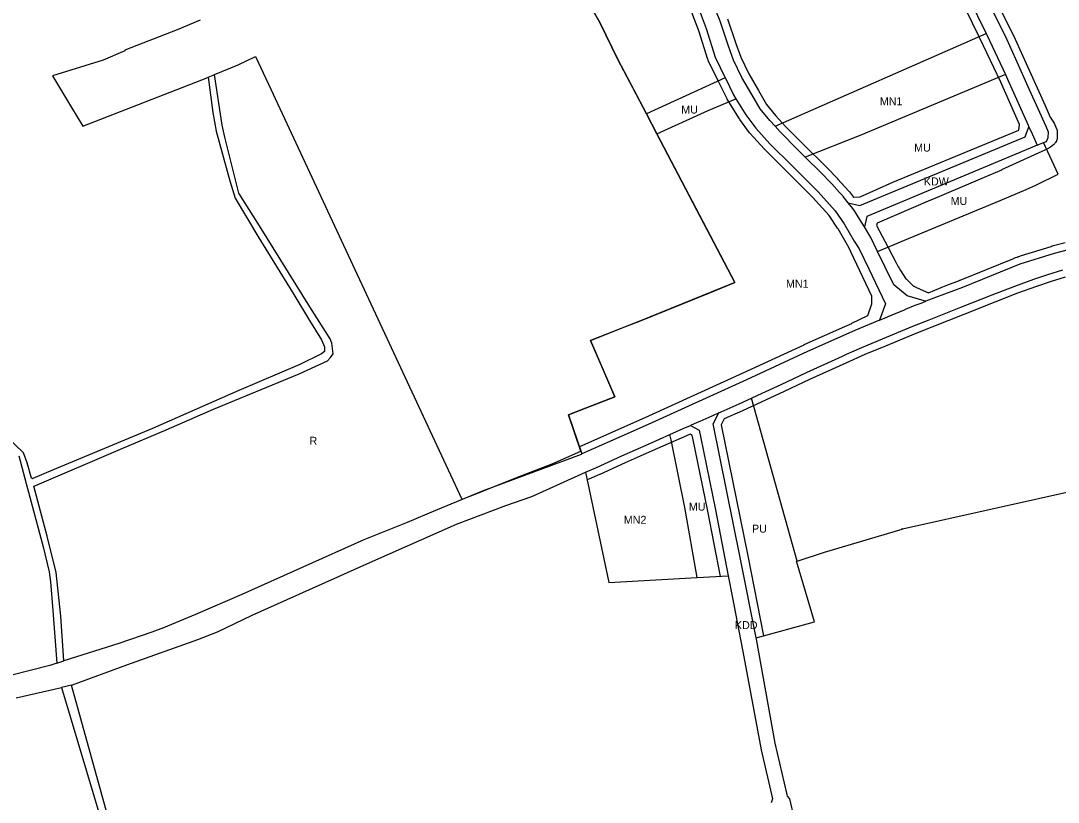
# Model space of a CAD drawing. Extents: x 7435758 to 7439981, y 5550649 to 5554049.
# Drawn here: x 7436433 to 7437107, y 5551221 to 5551729 of the extents above; entities that cross this region are included whole.
import ezdxf

# ---------------------------------------------------------------- set-up
doc = ezdxf.new("R2010")
doc.units = 0
for name, color, linetype in [('info', 7, 'Continuous'), ('linie_rozgraniczające', 7, 'Continuous'), ('linie_zabudowy_nieprzekraczalne', 7, 'Continuous'), ('oznaczenia_przeznaczen', 7, 'Continuous')]:
    doc.layers.add(name, color=color, linetype=linetype)

msp = doc.modelspace()

# ---------------------------------------------------------------- linework, layer by layer
at = {"layer": 'info'}
for p, q in [((7436549.92, 5551729.75), (7436534.97, 5551723.42)), ((7436554.78, 5551692.57), (7436555, 5551692.66)), ((7436594.25, 5551688.18), (7436720, 5551418.39)), ((7436839.8, 5551668.84), (7436830.9, 5551685.83)), ((7436846.57, 5551655.92), (7436839.8, 5551668.84)), ((7436872.6, 5551606.23), (7436846.57, 5551655.92)), ((7436834.79, 5551533.96), (7436880.27, 5551552.36)), ((7436825.84, 5551530.4), (7436834.79, 5551533.96)), ((7436819.25, 5551484.94), (7436811.4, 5551503.25)), ((7436808.77, 5551480.86), (7436819.25, 5551484.94))]:
    msp.add_line(p, q, dxfattribs=at)
for points in [[(7436830.9, 5551685.83), (7436821.23, 5551704.3), (7436809.54, 5551728.26), (7436800.79, 5551743.61)], [(7436534.97, 5551723.42), (7436500.87, 5551710.27), (7436500.89, 5551709.81), (7436486.9, 5551703.76), (7436453.97, 5551693.56), (7436466.32, 5551673), (7436473.75, 5551660.92), (7436554.78, 5551692.57)], [(7436559.23, 5551694.45), (7436574.58, 5551700.76), (7436585.89, 5551706.11), (7436585.89, 5551706.11), (7436594.25, 5551688.18)], [(7436555, 5551692.66), (7436558.29, 5551694.06), (7436559.23, 5551694.45)], [(7436880.27, 5551552.36), (7436897.23, 5551559.22), (7436872.6, 5551606.23)], [(7436811.4, 5551503.25), (7436803.56, 5551521.54), (7436825.84, 5551530.4)], [(7436797.24, 5551449.59), (7436789.24, 5551473.16), (7436800.3, 5551477.56), (7436808.77, 5551480.86)], [(7436733.94, 5551423.92), (7436756.16, 5551432.67), (7436778.56, 5551441.5), (7436797.24, 5551449.59)], [(7436720, 5551418.39), (7436720.74, 5551418.7), (7436733.47, 5551423.74)], [(7436733.47, 5551423.74), (7436733.75, 5551423.85), (7436733.94, 5551423.92)]]:
    msp.add_lwpolyline(points, dxfattribs=at)
at = {"layer": 'linie_rozgraniczające'}
for p, q in [((7436780.9, 5551778.49), (7436809.54, 5551728.26)), ((7437073.91, 5551717.41), (7437057.78, 5551750.11)), ((7436887.83, 5551729.05), (7436879.8, 5551748.53)), ((7437047.32, 5551748.47), (7437060.55, 5551721.15)), ((7436874, 5551736.55), (7436878.59, 5551724.44)), ((7436809.54, 5551728.26), (7436821.23, 5551704.3)), ((7436878.59, 5551724.44), (7436884.53, 5551705.83)), ((7436893.13, 5551712.87), (7436887.83, 5551729.05)), ((7436923.4, 5551660.79), (7437060.54, 5551721.14)), ((7437060.54, 5551721.14), (7437060.55, 5551721.14)), ((7437060.55, 5551721.15), (7437060.55, 5551721.14)), ((7437060.55, 5551721.14), (7437060.96, 5551720.27)), ((7437060.96, 5551720.27), (7437073.16, 5551694.4)), ((7437079.77, 5551704.39), (7437073.91, 5551717.41)), ((7436896.5, 5551703.72), (7436893.13, 5551712.87)), ((7436821.23, 5551704.3), (7436839.8, 5551668.84)), ((7436884.53, 5551705.83), (7436891.02, 5551692.32)), ((7436901.88, 5551692.46), (7436896.5, 5551703.72)), ((7437088.75, 5551684.44), (7437079.77, 5551704.39)), ((7436555, 5551692.66), (7436558.03, 5551669.7)), ((7436564.11, 5551661.5), (7436559.23, 5551694.45)), ((7436891.02, 5551692.32), (7436839.8, 5551668.84)), ((7436891.02, 5551692.32), (7436891.1, 5551692.16)), ((7436891.1, 5551692.16), (7436896.46, 5551681.18)), ((7436908.33, 5551681.52), (7436901.88, 5551692.46)), ((7437073.16, 5551694.4), (7436979.07, 5551654.95)), ((7437073.16, 5551694.4), (7437074.53, 5551691.49)), ((7437074.53, 5551691.49), (7437087.82, 5551661.62)), ((7437094.25, 5551672.21), (7437088.75, 5551684.44)), ((7436879.91, 5551671.09), (7436898.01, 5551678.68)), ((7436896.46, 5551681.18), (7436898.01, 5551678.68)), ((7436898.01, 5551678.68), (7436904.5, 5551668.25)), ((7436913.63, 5551672.17), (7436908.33, 5551681.52)), ((7436558.03, 5551669.7), (7436560.18, 5551657.72)), ((7436846.57, 5551655.92), (7436879.91, 5551671.09)), ((7436919.95, 5551664.5), (7436913.63, 5551672.17)), ((7437099.45, 5551660.63), (7437094.25, 5551672.21)), ((7436839.8, 5551668.84), (7436846.57, 5551655.92)), ((7436904.5, 5551668.25), (7436910.87, 5551659.49)), ((7436923.4, 5551660.79), (7436919.95, 5551664.5)), ((7436560.18, 5551657.72), (7436569.22, 5551625.29)), ((7436565.91, 5551653.74), (7436564.11, 5551661.5)), ((7436846.57, 5551655.92), (7436897.23, 5551559.22)), ((7436910.87, 5551659.49), (7436920.02, 5551649.48)), ((7436926.67, 5551657.26), (7436923.4, 5551660.79)), ((7436938.07, 5551645.7), (7436926.67, 5551657.26)), ((7437085.84, 5551653.87), (7437088.31, 5551660.53)), ((7437087.82, 5551661.62), (7437087.92, 5551661.39)), ((7437087.92, 5551661.39), (7437088.31, 5551660.53)), ((7437088.31, 5551660.53), (7437090.46, 5551655.79)), ((7437090.46, 5551655.79), (7437093.78, 5551648.48)), ((7437101.07, 5551657), (7437099.45, 5551660.63)), ((7437100.85, 5551653.56), (7437101.11, 5551656.93)), ((7437101.11, 5551656.93), (7437101.07, 5551657)), ((7436574.95, 5551617.32), (7436565.91, 5551653.74)), ((7436920.02, 5551649.48), (7436934.54, 5551635.04)), ((7436979.07, 5551654.95), (7436943.06, 5551640.76)), ((7436978.46, 5551609.25), (7437085.84, 5551653.87)), ((7437093.78, 5551648.48), (7437097.85, 5551650.19)), ((7437097.85, 5551650.19), (7437099.72, 5551650.97)), ((7437100.68, 5551644.24), (7437097.85, 5551650.19)), ((7437099.72, 5551650.97), (7437100.85, 5551653.56)), ((7436943.06, 5551640.76), (7436938.07, 5551645.7)), ((7437089.16, 5551646.55), (7436983.06, 5551602.18)), ((7437093.78, 5551648.48), (7437089.16, 5551646.55)), ((7437107.34, 5551629.66), (7437100.68, 5551644.24)), ((7436953.44, 5551630.48), (7436943.06, 5551640.76)), ((7436934.54, 5551635.04), (7436951.34, 5551618.24)), ((7436959.58, 5551624.12), (7436953.44, 5551630.48)), ((7437093.23, 5551622.83), (7437107.34, 5551629.66)), ((7436569.22, 5551625.29), (7436572.53, 5551614.07)), ((7436959.6, 5551624.1), (7436959.58, 5551624.12)), ((7436960.28, 5551623.38), (7436959.6, 5551624.1)), ((7436965.37, 5551617.79), (7436960.28, 5551623.38)), ((7437086.63, 5551619.64), (7437093.23, 5551622.83)), ((7436588.35, 5551596.16), (7436574.95, 5551617.32)), ((7436951.34, 5551618.24), (7436962.5, 5551605.85)), ((7436967.41, 5551615.56), (7436965.37, 5551617.79)), ((7436967.72, 5551615.21), (7436967.41, 5551615.56)), ((7436970.99, 5551611.01), (7436967.72, 5551615.21)), ((7437069.6, 5551612.53), (7437086.63, 5551619.64)), ((7436572.53, 5551614.07), (7436588.07, 5551588.32)), ((7436973.84, 5551607.33), (7436970.99, 5551611.01)), ((7436970.99, 5551611.01), (7436978.46, 5551609.25)), ((7437007.51, 5551586.69), (7437069.6, 5551612.53)), ((7436962.5, 5551605.85), (7436968.31, 5551597.34)), ((7436974.93, 5551605.94), (7436973.84, 5551607.33)), ((7436978.45, 5551600.25), (7436974.93, 5551605.94)), ((7436983.06, 5551602.18), (7436981.47, 5551595.36)), ((7436621.2, 5551543.41), (7436588.35, 5551596.16)), ((7436968.31, 5551597.34), (7436974.77, 5551586.13)), ((7436981.47, 5551595.36), (7436978.45, 5551600.25)), ((7436985.65, 5551588.61), (7436981.47, 5551595.36)), ((7436588.07, 5551588.32), (7436610.73, 5551551.38)), ((7436990.03, 5551579.48), (7436985.65, 5551588.61)), ((7436974.77, 5551586.13), (7436978.12, 5551581.08)), ((7436990.03, 5551579.48), (7437007.51, 5551586.69)), ((7436978.12, 5551581.08), (7436984.26, 5551568.21)), ((7436994.96, 5551569.19), (7436990.03, 5551579.48)), ((7437104.79, 5551578.17), (7437082.49, 5551571.18)), ((7437113.83, 5551580.57), (7437104.79, 5551578.17)), ((7436984.26, 5551568.21), (7436995.06, 5551545.39)), ((7437000.48, 5551557.66), (7436994.96, 5551569.19)), ((7437082.49, 5551571.18), (7437045.16, 5551556.09)), ((7437079.18, 5551556.96), (7437091.55, 5551561.49)), ((7437091.55, 5551561.49), (7437100.72, 5551564.52)), ((7437100.72, 5551564.52), (7437110.46, 5551567.5)), ((7436897.23, 5551559.22), (7436834.79, 5551533.96)), ((7437009.3, 5551550.61), (7437000.48, 5551557.66)), ((7437045.16, 5551556.09), (7437027.68, 5551549.46)), ((7437064.45, 5551551.19), (7437079.18, 5551556.96)), ((7436610.73, 5551551.38), (7436620.92, 5551534.56)), ((7437020.18, 5551547.38), (7437009.3, 5551550.61)), ((7437023.04, 5551547.7), (7437021.33, 5551547.05)), ((7437027.68, 5551549.46), (7437023.04, 5551547.7)), ((7437044.18, 5551543.2), (7437064.45, 5551551.19)), ((7436634.35, 5551522.76), (7436621.2, 5551543.41)), ((7436995.06, 5551545.39), (7436991.25, 5551534.79)), ((7436999.58, 5551538.26), (7437007.57, 5551541.59)), ((7437007.57, 5551541.59), (7437007.84, 5551541.7)), ((7437007.84, 5551541.7), (7437008.24, 5551541.87)), ((7437008.24, 5551541.87), (7437014.42, 5551544.44)), ((7437014.42, 5551544.44), (7437018.27, 5551545.9)), ((7437018.27, 5551545.9), (7437021.33, 5551547.05)), ((7437021.33, 5551547.05), (7437020.18, 5551547.38)), ((7437023.43, 5551534.98), (7437044.18, 5551543.2)), ((7436620.92, 5551534.56), (7436628.68, 5551521.98)), ((7436991.25, 5551534.79), (7436975.24, 5551528.13)), ((7436991.25, 5551534.79), (7436994.85, 5551536.29)), ((7436994.85, 5551536.29), (7436998.34, 5551537.74)), ((7436998.34, 5551537.74), (7436998.62, 5551537.86)), ((7436998.62, 5551537.86), (7436999.58, 5551538.26)), ((7437012.97, 5551530.78), (7437023.43, 5551534.98)), ((7436834.79, 5551533.96), (7436803.56, 5551521.54)), ((7436975.24, 5551528.13), (7436944.46, 5551514.32)), ((7436993.26, 5551522.6), (7437012.97, 5551530.78)), ((7436628.68, 5551521.98), (7436630.64, 5551517.54)), ((7436635.53, 5551519.76), (7436634.35, 5551522.76)), ((7436803.56, 5551521.54), (7436819.25, 5551484.94)), ((7436979.75, 5551516.99), (7436993.26, 5551522.6)), ((7436630.77, 5551514.46), (7436628.7, 5551512.83)), ((7436630.64, 5551517.54), (7436630.77, 5551514.46)), ((7436636.34, 5551512.91), (7436635.53, 5551519.76)), ((7436944.46, 5551514.32), (7436904.86, 5551495.96)), ((7436969.84, 5551512.59), (7436979.75, 5551516.99)), ((7436614.1, 5551499.83), (7436632.56, 5551508.26)), ((7436628.7, 5551512.83), (7436614.59, 5551505.95)), ((7436632.56, 5551508.26), (7436634.58, 5551510.45)), ((7436634.58, 5551510.45), (7436636.34, 5551512.91)), ((7436943.73, 5551500.73), (7436967.25, 5551511.44)), ((7436967.25, 5551511.44), (7436969.84, 5551512.59)), ((7436614.59, 5551505.95), (7436574.99, 5551489.01)), ((7436927.29, 5551493.04), (7436943.73, 5551500.73)), ((7436558.6, 5551476.88), (7436614.1, 5551499.83)), ((7436904.86, 5551495.96), (7436843.44, 5551467.97)), ((7436574.99, 5551489.01), (7436518.82, 5551464.33)), ((7436912.27, 5551485.93), (7436927.29, 5551493.04)), ((7436819.25, 5551484.94), (7436800.3, 5551477.56)), ((7436888.4, 5551475.2), (7436900.15, 5551480.36)), ((7436900.15, 5551480.36), (7436908.19, 5551484.06)), ((7436908.19, 5551484.06), (7436912.27, 5551485.93)), ((7436937.68, 5551378.18), (7436908.19, 5551484.06)), ((7436527.79, 5551463.61), (7436558.6, 5551476.88)), ((7436800.3, 5551477.56), (7436789.24, 5551473.16)), ((7436886.77, 5551474.48), (7436882.22, 5551472.45)), ((7436883.22, 5551467.5), (7436886.77, 5551474.48)), ((7436886.77, 5551474.48), (7436888.4, 5551475.2)), ((7436435.07, 5551448.64), (7436413.62, 5551469.2)), ((7436789.24, 5551473.16), (7436797.85, 5551447.8)), ((7436843.44, 5551467.97), (7436829.23, 5551461.68)), ((7436872.87, 5551468.29), (7436868.46, 5551466.35)), ((7436874.49, 5551469.01), (7436872.87, 5551468.29)), ((7436882.22, 5551472.45), (7436874.49, 5551469.01)), ((7436900.79, 5551380.63), (7436883.22, 5551467.5)), ((7436518.82, 5551464.33), (7436453.95, 5551437.28)), ((7436498.1, 5551450.94), (7436527.79, 5551463.61)), ((7436829.23, 5551461.68), (7436797.85, 5551447.8)), ((7436841.55, 5551454.42), (7436855.1, 5551460.42)), ((7436855.1, 5551460.42), (7436863.74, 5551464.27)), ((7436855.96, 5551457), (7436855.1, 5551460.42)), ((7436863.74, 5551464.27), (7436868.46, 5551466.35)), ((7436868.46, 5551466.35), (7436874, 5551463.32)), ((7436874, 5551463.32), (7436874.95, 5551459.15)), ((7436823.94, 5551446.54), (7436841.55, 5551454.42)), ((7436864.75, 5551412.96), (7436855.96, 5551457)), ((7436874.95, 5551459.15), (7436884.6, 5551411.54)), ((7437006.21, 5551399.25), (7437262.51, 5551456.29)), ((7436432.01, 5551446.56), (7436436.88, 5551428.6)), ((7436437.59, 5551442.08), (7436435.07, 5551448.64)), ((7436442.48, 5551427.13), (7436498.1, 5551450.94)), ((7436797.32, 5551447.57), (7436733.75, 5551423.85)), ((7436797.85, 5551447.8), (7436797.32, 5551447.57)), ((7436807.42, 5551439.12), (7436823.94, 5551446.54)), ((7436440.26, 5551432.13), (7436437.59, 5551442.08)), ((7436453.95, 5551437.28), (7436441.1, 5551431.82)), ((7436765.27, 5551420.25), (7436800.29, 5551435.97)), ((7436800.29, 5551435.97), (7436807.42, 5551439.12)), ((7436800.29, 5551435.97), (7436815.43, 5551364.36)), ((7436436.88, 5551428.6), (7436447.86, 5551387.37)), ((7436441.04, 5551431.6), (7436440.26, 5551432.13)), ((7436441.1, 5551431.82), (7436441.04, 5551431.6)), ((7436441.81, 5551426.81), (7436442.48, 5551427.13)), ((7436450.47, 5551394.33), (7436441.81, 5551426.81)), ((7436733.75, 5551423.85), (7436702.82, 5551411.17)), ((7436748.57, 5551414.38), (7436765.27, 5551420.25)), ((7436732.51, 5551408.24), (7436748.57, 5551414.38)), ((7436872.7, 5551367.51), (7436864.75, 5551412.96)), ((7436702.82, 5551411.17), (7436684.32, 5551403.37)), ((7436716.33, 5551402.22), (7436732.51, 5551408.24)), ((7436884.6, 5551411.54), (7436893.04, 5551368.63)), ((7436684.32, 5551403.37), (7436656.21, 5551391.97)), ((7436662.06, 5551378.16), (7436716.33, 5551402.22)), ((7437006.02, 5551398.84), (7437005.84, 5551399.4)), ((7437005.84, 5551399.4), (7437006.21, 5551399.25)), ((7436456.33, 5551370.68), (7436450.47, 5551394.33)), ((7436955.53, 5551384.01), (7437006.02, 5551398.84)), ((7436447.86, 5551387.37), (7436451.78, 5551371.19)), ((7436656.21, 5551391.97), (7436576.92, 5551356.38)), ((7436911.09, 5551328.35), (7436900.79, 5551380.63)), ((7436937.68, 5551378.18), (7436955.53, 5551384.01)), ((7436583.63, 5551343.04), (7436662.06, 5551378.16)), ((7436937.41, 5551378.09), (7436937.68, 5551378.18)), ((7436948.99, 5551338.64), (7436937.41, 5551378.09)), ((7436451.78, 5551371.19), (7436452.55, 5551364.81)), ((7436459.36, 5551342.4), (7436456.33, 5551370.68)), ((7436815.43, 5551364.36), (7436872.7, 5551367.51)), ((7436872.7, 5551367.51), (7436893.04, 5551368.63)), ((7436893.04, 5551368.63), (7436895.84, 5551354.37)), ((7436452.55, 5551364.81), (7436454.06, 5551346.02)), ((7436576.92, 5551356.38), (7436546.75, 5551343.54)), ((7436895.84, 5551354.37), (7436903.11, 5551315.88)), ((7436454.06, 5551346.02), (7436456.86, 5551311.89)), ((7436461.4, 5551313.33), (7436459.36, 5551342.4)), ((7436546.75, 5551343.54), (7436525.97, 5551334.91)), ((7436561.17, 5551332.2), (7436583.63, 5551343.04)), ((7436518.57, 5551331.97), (7436497.08, 5551324.64)), ((7436525.97, 5551334.91), (7436518.57, 5551331.97)), ((7436548.45, 5551327.28), (7436561.17, 5551332.2)), ((7436911.09, 5551328.35), (7436948.99, 5551338.64)), ((7436502.25, 5551310.66), (7436548.45, 5551327.28)), ((7436911.26, 5551327.44), (7436911.09, 5551328.35)), ((7436923.53, 5551259.89), (7436911.26, 5551327.44)), ((7436497.08, 5551324.64), (7436461.4, 5551313.33)), ((7436456.86, 5551311.89), (7436452.23, 5551310.42)), ((7436456.86, 5551311.89), (7436461.4, 5551313.33)), ((7436903.11, 5551315.88), (7436914.38, 5551255.61)), ((7436452.23, 5551310.42), (7436426.71, 5551303.89)), ((7436466.89, 5551297.66), (7436502.25, 5551310.66)), ((7436430.38, 5551289.37), (7436459.7, 5551296.03)), ((7436466.37, 5551297.54), (7436459.7, 5551296.03)), ((7436459.7, 5551296.03), (7436509.03, 5551131.65)), ((7436466.37, 5551297.54), (7436466.89, 5551297.66)), ((7436496.23, 5551189.45), (7436466.37, 5551297.54)), ((7436931.05, 5551227.33), (7436923.53, 5551259.89)), ((7436914.38, 5551255.61), (7436921.72, 5551223.76)), ((7436931.29, 5551226.25), (7436931.05, 5551227.33)), ((7436931.48, 5551225.45), (7436931.29, 5551226.25)), ((7436933.05, 5551223.72), (7436931.48, 5551225.45)), ((7436921.72, 5551223.76), (7436920.85, 5551220.99)), ((7436935.81, 5551211.44), (7436933.05, 5551223.72))]:
    msp.add_line(p, q, dxfattribs=at)
at = {"layer": 'linie_zabudowy_nieprzekraczalne'}
for points in [[(7437007.31, 5551859.42), (7437009.85, 5551853.53), (7437024.38, 5551825.98), (7437038.5, 5551800.8), (7437038.53, 5551800.75), (7437038.63, 5551800.55), (7437048.95, 5551779.47), (7437062.27, 5551752.32), (7437078.39, 5551719.62), (7437078.45, 5551719.51), (7437078.47, 5551719.46), (7437084.33, 5551706.44), (7437098.81, 5551674.26), (7437098.81, 5551674.26), (7437102.22, 5551666.67), (7437104.72, 5551662.82)], [(7436892.58, 5551730.61), (7436897.85, 5551714.51), (7436901.12, 5551705.67), (7436906.3, 5551694.81), (7436912.64, 5551684.06), (7436912.68, 5551683.99), (7436917.77, 5551675.02), (7436923.72, 5551667.8), (7436930.28, 5551660.72), (7436941.61, 5551649.24), (7436956.96, 5551634.03), (7436957.04, 5551633.95), (7436963.88, 5551626.85), (7436963.91, 5551626.83), (7436963.98, 5551626.75), (7436971.42, 5551618.58), (7436971.56, 5551618.41), (7436971.67, 5551618.28), (7436974.46, 5551614.69), (7436974.53, 5551614.7), (7436978.64, 5551614.86), (7436999.83, 5551624.45), (7437081.72, 5551658.38), (7437082.16, 5551662.03), (7437069.99, 5551689.41), (7437056.44, 5551718.14), (7437056.43, 5551718.15), (7437056.03, 5551719), (7437042.82, 5551746.29)], [(7436964.42, 5551594.07), (7436964.07, 5551594.68), (7436958.56, 5551602.75), (7436947.71, 5551614.79), (7436931, 5551631.51), (7436916.49, 5551645.93), (7436916.4, 5551646.03), (7436916.33, 5551646.11), (7436907.18, 5551656.12), (7436907.03, 5551656.29), (7436906.83, 5551656.55), (7436906.82, 5551656.55), (7436900.46, 5551665.31), (7436900.26, 5551665.61), (7436892.22, 5551678.53), (7436892.07, 5551678.78), (7436891.97, 5551678.98), (7436886.61, 5551689.97), (7436886.59, 5551690), (7436880.03, 5551703.66), (7436880, 5551703.73), (7436879.87, 5551704.03), (7436879.77, 5551704.31), (7436873.86, 5551722.79), (7436869.36, 5551734.67)], [(7437104.72, 5551662.82), (7437106.32, 5551659.22), (7437106.43, 5551658.98), (7437106.53, 5551658.67), (7437106.62, 5551658.36), (7437106.69, 5551658.03), (7437106.73, 5551657.71), (7437106.76, 5551657.38), (7437106.76, 5551657.13), (7437106.72, 5551653.44), (7437106.72, 5551653.37), (7437106.7, 5551653.04), (7437106.66, 5551652.72), (7437106.6, 5551652.4), (7437106.52, 5551652.08), (7437106.42, 5551651.77), (7437106.29, 5551651.46), (7437106.15, 5551651.17), (7437106.04, 5551650.97), (7437105.67, 5551650.34), (7437105.62, 5551650.26), (7437105.44, 5551649.98), (7437105.25, 5551649.72), (7437105.03, 5551649.47), (7437104.8, 5551649.24), (7437104.56, 5551649.02), (7437104.46, 5551648.94), (7437102.3, 5551647.24), (7437102.15, 5551647.12), (7437101.88, 5551646.93), (7437101.59, 5551646.77), (7437101.35, 5551646.64), (7437099.09, 5551645.57), (7437099.05, 5551645.55), (7437099.04, 5551645.55), (7437070.52, 5551632.41), (7437070.45, 5551632.38), (7437062.31, 5551628.77), (7437062.22, 5551628.73), (7437024.51, 5551612.86), (7437024.5, 5551612.86), (7436989.8, 5551597.75), (7436989.35, 5551596.29)], [(7436989.35, 5551596.29), (7436996.74, 5551582.47), (7436999.57, 5551577.06), (7437002.17, 5551571.96)], [(7436968.79, 5551530.71), (7436973.19, 5551532.69), (7436973.32, 5551532.74), (7436983.7, 5551537.74), (7436986.34, 5551545.3), (7436986.31, 5551550.46), (7436970.61, 5551583.36), (7436970.55, 5551583.45), (7436970.44, 5551583.63), (7436964.42, 5551594.07)], [(7437002.17, 5551571.96), (7437002.54, 5551571.22), (7437003.47, 5551569.5), (7437004.01, 5551568.57), (7437004.96, 5551567.05), (7437008.46, 5551561.6), (7437008.48, 5551561.58), (7437008.49, 5551561.57), (7437013.18, 5551557.08), (7437013.3, 5551557.02), (7437013.42, 5551556.96), (7437013.63, 5551556.83), (7437015.73, 5551555.87), (7437023.14, 5551552.64), (7437023.14, 5551552.64), (7437023.16, 5551552.64), (7437031.32, 5551556.05), (7437035.7, 5551557.81), (7437043.14, 5551560.67), (7437043.34, 5551560.75), (7437043.69, 5551560.89), (7437077.82, 5551574.68), (7437079.68, 5551575.44), (7437080.68, 5551575.84), (7437080.69, 5551575.84), (7437080.98, 5551575.95), (7437081.27, 5551576.04), (7437081.83, 5551576.21), (7437083.5, 5551576.74), (7437102.73, 5551582.77), (7437103.3, 5551582.95), (7437103.5, 5551583.01), (7437103.62, 5551583.04), (7437104.3, 5551583.22), (7437111.87, 5551585.22)], [(7437111.79, 5551562.68), (7437102.24, 5551559.75), (7437093.19, 5551556.77), (7437080.95, 5551552.29), (7437066.27, 5551546.54), (7437046.01, 5551538.55), (7437025.28, 5551530.34), (7437014.86, 5551526.15), (7436995.18, 5551517.99), (7436981.72, 5551512.39), (7436969.29, 5551506.88), (7436945.83, 5551496.2), (7436929.42, 5551488.51), (7436914.41, 5551481.41), (7436914.37, 5551481.39), (7436914.35, 5551481.38), (7436902.24, 5551475.82), (7436902.16, 5551475.79), (7436890.43, 5551470.63), (7436890.42, 5551470.63), (7436888.47, 5551466.79), (7436905.69, 5551381.62), (7436905.69, 5551381.59), (7436915.93, 5551329.65)], [(7436827.24, 5551466.3), (7436841.39, 5551472.53), (7436902.77, 5551500.51), (7436942.36, 5551518.85), (7436942.36, 5551518.86), (7436942.42, 5551518.88), (7436968.79, 5551530.71)], [(7436796.65, 5551452.74), (7436827.26, 5551466.28)], [(7436888.02, 5551368.24), (7436879.7, 5551410.57), (7436870.07, 5551458.1), (7436869.63, 5551460.01), (7436868.22, 5551460.78), (7436865.76, 5551459.7), (7436843.59, 5551449.85), (7436825.98, 5551441.97), (7436809.47, 5551434.56), (7436809.44, 5551434.55), (7436802.32, 5551431.4), (7436801.37, 5551430.97)]]:
    msp.add_lwpolyline(points, dxfattribs=at)

# ---------------------------------------------------------------- texts
at = {"layer": 'oznaczenia_przeznaczen'}
for s, p in [('MN1', (7436991.47, 5551674.5)), ('MU', (7436862.46, 5551669.07)), ('MU', (7437013.75, 5551644.33)), ('KDW', (7437020.07, 5551622.33)), ('MU', (7437037.49, 5551609.66)), ('MN1', (7436930.52, 5551555.84)), ('R', (7436620.93, 5551453.77)), ('MU', (7436867.38, 5551410.99)), ('MN2', (7436825.12, 5551402.42)), ('PU', (7436908.43, 5551396.68)), ('KDD', (7436897.31, 5551333.97))]:
    msp.add_text(s, height=5.2, dxfattribs=at).set_placement(p)

doc.saveas('drawing.dxf')
